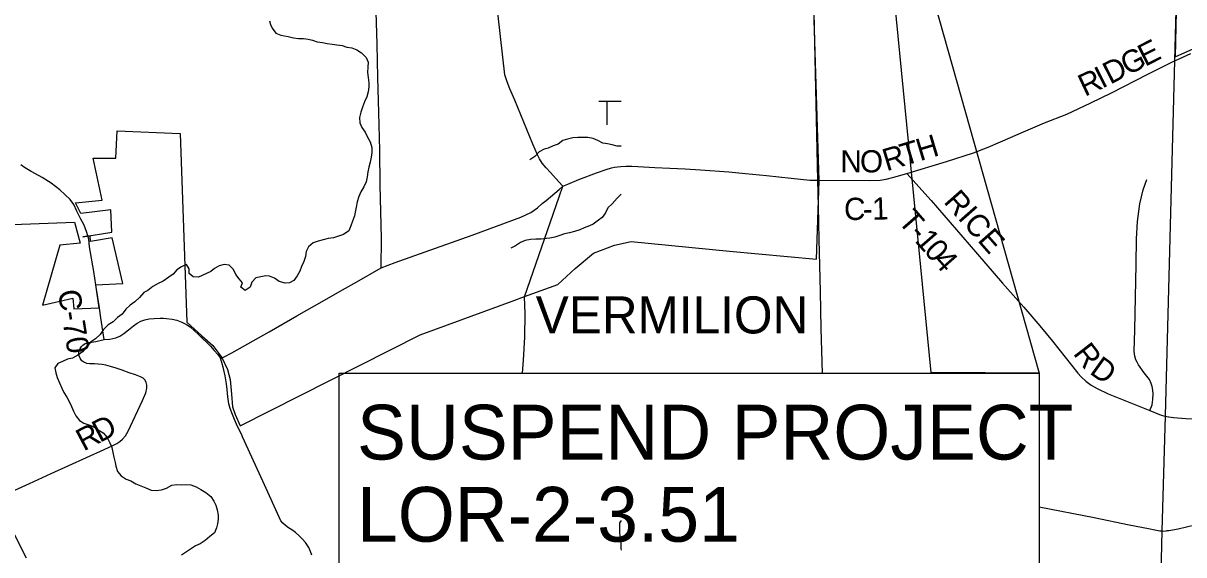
# Model space of a CAD drawing. Extents: x 0 to 34, y 0 to 22.
# Drawn here: x 10.012 to 12.978, y 7.409 to 8.768 of the extents above; entities that cross this region are included whole.
import ezdxf

# ---------------------------------------------------------------- set-up
doc = ezdxf.new("R2010")
doc.units = 0
for name, color, linetype in [('GM_X_City_Street', 7, 'Continuous'), ('GM_X_Corporation', 7, 'Continuous'), ('GM_X_Corporation_Text', 7, 'Continuous'), ('GM_X_County_Road', 7, 'Continuous'), ('GM_X_County_Road_Text', 7, 'Continuous'), ('GM_X_Minor_River', 7, 'Continuous'), ('GM_X_Rail_Line', 7, 'Continuous'), ('GM_X_Township_Road', 7, 'Continuous'), ('GM_X_Township_Road_Text', 7, 'Continuous'), ('SH_Text', 7, 'Continuous')]:
    doc.layers.add(name, color=color, linetype=linetype)

msp = doc.modelspace()

# ---------------------------------------------------------------- linework, layer by layer
at = {"layer": 'GM_X_City_Street'}
msp.add_line((11.5049, 8.5085), (11.5047, 8.5684), dxfattribs=at)
msp.add_lwpolyline([(11.4832, 8.5689), (11.5047, 8.5684), (11.5404, 8.5686)], dxfattribs=at)
at = {"layer": 'GM_X_Corporation'}
for points in [[(12.9927, 10.4066), (12.9728, 9.4593), (12.9564, 8.6818), (13.0041, 8.7033)], [(9.9393, 8.2516), (10.1436, 8.2595), (10.1579, 8.206), (10.1055, 8.2004), (10.0617, 8.0476), (10.1393, 8.0651), (10.1419, 8.0378), (10.2067, 8.041), (10.1977, 8.0993), (10.2671, 8.1024), (10.2396, 8.2192), (10.1846, 8.21), (10.183, 8.225), (10.1645, 8.2225), (10.239, 8.2343), (10.2363, 8.2912), (10.1593, 8.2814), (10.1456, 8.3093), (10.2138, 8.3154), (10.1907, 8.4233), (10.2493, 8.4233), (10.2524, 8.493), (10.4135, 8.4866), (10.4306, 8.0042), (10.4691, 7.9694), (10.497, 7.944), (10.52, 7.9137), (10.534, 7.8827), (10.5411, 7.8576), (10.5446, 7.82), (10.5471, 7.7872), (10.554, 7.7677), (10.5669, 7.7388), (11.0268, 7.9716), (11.2619, 8.0576), (11.2934, 8.0692), (11.3788, 8.1005), (11.4227, 8.1414), (11.47, 8.1805), (11.5231, 8.2005), (11.5663, 8.2099), (11.8168, 8.1857), (12.0394, 8.1648), (12.0462, 8.3651), (12.0135, 9.4352)]]:
    msp.add_lwpolyline(points, dxfattribs=at)
at = {"layer": 'GM_X_County_Road'}
msp.add_line((12.033, 8.3673), (12.0431, 8.3673), dxfattribs=at)
for points in [[(12.0463, 8.2153), (12.0443, 8.3007), (12.0431, 8.3673), (12.0305, 8.953), (12.0238, 9.0638)], [(10.9274, 8.1427), (10.9276, 8.2181), (10.9246, 8.3546), (10.9237, 8.443), (10.9207, 8.5401), (10.9187, 8.6294), (10.9172, 8.7146), (10.9133, 8.8248)], [(12.9572, 8.6731), (12.9961, 8.6909)], [(12.0431, 8.3673), (12.1746, 8.3657), (12.2024, 8.3671), (12.2179, 8.3697), (12.2371, 8.3747), (12.2708, 8.384), (12.372, 8.4143), (12.4412, 8.437), (12.4782, 8.4513), (12.5099, 8.4649), (12.5746, 8.4933), (12.6224, 8.5131), (12.6789, 8.536), (12.7407, 8.5642), (12.7935, 8.5897), (12.8863, 8.6382), (12.9544, 8.6719), (12.9572, 8.6731)], [(10.1978, 8.0997), (10.1928, 8.1335), (10.182, 8.1966), (10.1795, 8.2161), (10.175, 8.2334), (10.1677, 8.2519), (10.1593, 8.2676), (10.1492, 8.2881), (10.1412, 8.3049), (10.1318, 8.3177), (10.1186, 8.3306), (10.1057, 8.342), (10.0838, 8.359), (10.0607, 8.3735), (10.044, 8.3831), (10.0327, 8.3887), (10.0152, 8.3993), (10.0059, 8.4059)], [(11.3909, 8.3514), (11.4039, 8.3568), (11.4325, 8.3686), (11.4772, 8.3853), (11.502, 8.3939), (11.5153, 8.3983), (11.5232, 8.4), (11.531, 8.4013), (11.5394, 8.402), (11.5524, 8.4025), (11.5672, 8.4025), (11.5831, 8.4018), (11.6261, 8.3991), (11.6645, 8.3976), (11.7041, 8.3963), (11.7434, 8.3936), (11.8154, 8.3885), (11.8584, 8.3843), (11.9122, 8.3786), (11.9752, 8.3723), (12.0229, 8.3673), (12.033, 8.3673)], [(11.3711, 8.3338), (11.3823, 8.343), (11.3909, 8.3514)], [(10.5256, 7.9157), (10.5451, 7.9252), (10.6405, 7.9797), (10.7113, 8.02), (10.7821, 8.0603), (10.8279, 8.0863), (10.8647, 8.1072), (10.9274, 8.1427), (10.963, 8.1565), (11.0129, 8.1741), (11.1596, 8.2267), (11.2842, 8.2722), (11.3091, 8.2843), (11.3263, 8.2966), (11.3388, 8.3071), (11.3486, 8.3152), (11.3711, 8.3338)], [(12.0545, 7.8736), (12.0514, 7.9876), (12.0494, 8.0827), (12.0463, 8.2153)], [(10.2071, 8.0394), (10.207, 8.0404), (10.1987, 8.0938), (10.198, 8.0987), (10.1978, 8.0997)], [(10.2192, 7.9594), (10.2109, 8.0151), (10.2071, 8.0394)], [(10.2192, 7.9594), (10.2332, 7.9608), (10.2487, 7.964), (10.2593, 7.9684), (10.2694, 7.9748), (10.2816, 7.9844), (10.2944, 7.995), (10.3033, 8.0014), (10.3129, 8.0063), (10.3229, 8.0097), (10.334, 8.0122), (10.3473, 8.0136), (10.3623, 8.0141), (10.3709, 8.0144), (10.3785, 8.0134), (10.393, 8.0117), (10.405, 8.0087), (10.4176, 8.0043), (10.4291, 7.9982), (10.4385, 7.9918), (10.4498, 7.9822), (10.4591, 7.9733), (10.4712, 7.9618), (10.4798, 7.9534), (10.4906, 7.9426), (10.5004, 7.932), (10.51, 7.9215), (10.5162, 7.9117)], [(10.3034, 7.8675), (10.2989, 7.8691), (10.2834, 7.8745), (10.2654, 7.8809), (10.2497, 7.8866), (10.2354, 7.891), (10.2234, 7.8942), (10.2136, 7.8959), (10.2037, 7.8964), (10.1946, 7.8971), (10.1826, 7.8974), (10.175, 7.8984), (10.1669, 7.9018), (10.1622, 7.9055), (10.1583, 7.9107), (10.1556, 7.918), (10.1546, 7.9247), (10.1556, 7.9318), (10.1575, 7.9365), (10.161, 7.9421), (10.1649, 7.9456), (10.1706, 7.9492), (10.1806, 7.952), (10.1981, 7.9544), (10.2192, 7.9594)], [(10.5162, 7.9117), (10.5202, 7.9132), (10.5256, 7.9157)], [(10.5727, 7.7108), (10.5714, 7.7135), (10.5577, 7.7435), (10.5525, 7.7556), (10.5469, 7.7676), (10.5415, 7.7831), (10.538, 7.7954), (10.5351, 7.8133), (10.5336, 7.8315), (10.5319, 7.8467), (10.5287, 7.8672), (10.5242, 7.8856), (10.5201, 7.9011), (10.5162, 7.9117)], [(9.9533, 7.5576), (10.028, 7.5914), (10.084, 7.6169), (10.1737, 7.6585), (10.2187, 7.6784), (10.2413, 7.6889), (10.2514, 7.6941), (10.2588, 7.699), (10.2662, 7.7052), (10.2733, 7.7133), (10.2807, 7.7256), (10.317, 7.8042), (10.3252, 7.8234), (10.3279, 7.8354), (10.3281, 7.8433), (10.3266, 7.8497), (10.3237, 7.8558), (10.319, 7.8605), (10.3116, 7.8647), (10.3034, 7.8675)], [(10.7496, 7.4085), (10.7467, 7.4181), (10.7418, 7.4282), (10.7334, 7.4409), (10.7251, 7.45), (10.7167, 7.4584), (10.7081, 7.4668), (10.699, 7.4731), (10.6902, 7.4786), (10.6823, 7.4844), (10.6754, 7.4903), (10.6706, 7.4962), (10.6246, 7.5972), (10.5727, 7.7108)]]:
    msp.add_lwpolyline(points, dxfattribs=at)
at = {"layer": 'GM_X_Minor_River'}
for points in [[(10.6414, 8.7743), (10.6445, 8.7648), (10.6484, 8.755), (10.6576, 8.7429), (10.6706, 8.7377), (10.6801, 8.7355), (10.6896, 8.7344), (10.7026, 8.7311), (10.7159, 8.7293), (10.7288, 8.7287), (10.7402, 8.7273), (10.7516, 8.7247), (10.7638, 8.7206), (10.7768, 8.7188), (10.7893, 8.7159), (10.8019, 8.7141), (10.8137, 8.7131), (10.827, 8.7113), (10.8396, 8.7072), (10.8522, 8.7047), (10.8647, 8.7002), (10.8766, 8.6927), (10.8888, 8.6807), (10.8935, 8.6689), (10.8929, 8.656), (10.8922, 8.6423), (10.8938, 8.629), (10.8955, 8.6153), (10.8955, 8.6058), (10.8938, 8.5928), (10.8901, 8.5802), (10.8845, 8.5672), (10.8792, 8.5539), (10.8748, 8.5405), (10.8719, 8.5272), (10.8724, 8.5138), (10.8774, 8.5017), (10.8862, 8.4892), (10.8924, 8.4767), (10.8986, 8.4646), (10.9029, 8.4506), (10.9034, 8.4376), (10.9016, 8.4258), (10.8986, 8.4129), (10.8953, 8.3999), (10.8928, 8.3881), (10.891, 8.3755), (10.8884, 8.3625), (10.8828, 8.3499), (10.8749, 8.3373), (10.8701, 8.3251), (10.866, 8.3114), (10.8627, 8.298), (10.8602, 8.2854), (10.8587, 8.2759), (10.8539, 8.2622), (10.8491, 8.2499), (10.8446, 8.2373), (10.831, 8.2281), (10.8177, 8.2238), (10.8048, 8.2195), (10.7915, 8.2174), (10.7786, 8.2143), (10.7661, 8.2107), (10.7532, 8.2064), (10.7412, 8.1964), (10.7356, 8.1842), (10.7338, 8.1716), (10.7297, 8.159), (10.7237, 8.1464), (10.7192, 8.1342), (10.7121, 8.122), (10.7035, 8.1105), (10.6929, 8.1047), (10.6815, 8.1034), (10.6666, 8.1082), (10.6544, 8.1161), (10.6418, 8.1213), (10.6319, 8.1224), (10.6198, 8.1196), (10.6065, 8.1172), (10.5963, 8.1065), (10.5922, 8.0931), (10.5794, 8.0846), (10.5683, 8.0936), (10.5724, 8.1043), (10.5643, 8.1149), (10.5559, 8.1259), (10.55, 8.1388), (10.5389, 8.1497), (10.526, 8.1511)], [(11.5404, 8.4538), (11.5303, 8.4537), (11.5173, 8.457), (11.5051, 8.4596), (11.4937, 8.4618), (11.4811, 8.4682), (11.4689, 8.4738), (11.4552, 8.4756), (11.4415, 8.4759), (11.4293, 8.4762), (11.4168, 8.475), (11.4031, 8.4719), (11.3917, 8.468), (11.3796, 8.4591), (11.3668, 8.4549), (11.3539, 8.4487), (11.344, 8.4463), (11.3308, 8.439), (11.3195, 8.4275), (11.307, 8.4191)], [(11.5404, 8.331), (11.5401, 8.3309), (11.5299, 8.3205), (11.5171, 8.3067), (11.5061, 8.296), (11.5002, 8.2834), (11.4919, 8.2719), (11.4821, 8.2646), (11.4692, 8.2543), (11.4594, 8.2504), (11.4461, 8.245), (11.4344, 8.2403), (11.4207, 8.2357), (11.4082, 8.2322), (11.3957, 8.2294), (11.3835, 8.2255), (11.371, 8.2216), (11.3581, 8.2185), (11.3483, 8.2177), (11.3361, 8.2161), (11.3224, 8.216), (11.3083, 8.2151), (11.2954, 8.2128), (11.2829, 8.2073), (11.2705, 8.1993), (11.2583, 8.1931)], [(10.4915, 8.1338), (10.4601, 8.1193), (10.4464, 8.1196), (10.4361, 8.1282), (10.4364, 8.14), (10.4295, 8.151), (10.417, 8.1455), (10.4049, 8.1378), (10.3958, 8.1263), (10.3841, 8.119), (10.3697, 8.109), (10.3569, 8.1024), (10.3436, 8.095), (10.3304, 8.085), (10.3206, 8.08), (10.3096, 8.0673), (10.2979, 8.0562), (10.2855, 8.0477), (10.2742, 8.0369), (10.2651, 8.0247), (10.2534, 8.0162), (10.2417, 8.0051), (10.2289, 7.9969), (10.2176, 7.985), (10.2085, 7.9728), (10.1969, 7.9616), (10.1844, 7.9528), (10.1738, 7.9405), (10.1641, 7.9279), (10.1516, 7.9194), (10.1383, 7.9124), (10.1254, 7.9096), (10.1126, 7.9038), (10.1004, 7.8984), (10.0929, 7.8876), (10.0957, 7.8747), (10.0988, 7.8622), (10.105, 7.8489), (10.1108, 7.8357), (10.1159, 7.8243), (10.1236, 7.8122), (10.1305, 7.7997), (10.1359, 7.7883), (10.141, 7.7762), (10.1468, 7.7648), (10.156, 7.7531), (10.1675, 7.746), (10.18, 7.7416), (10.1915, 7.7375), (10.2037, 7.7288), (10.2163, 7.7213), (10.2267, 7.7089), (10.234, 7.6952), (10.2387, 7.6835), (10.2411, 7.6709), (10.2434, 7.6592), (10.2473, 7.6455), (10.2493, 7.6356), (10.2536, 7.622), (10.2624, 7.611), (10.2751, 7.6031), (10.2873, 7.5983), (10.3002, 7.5912), (10.3125, 7.586), (10.3254, 7.5804), (10.3388, 7.5748), (10.3517, 7.5734), (10.3654, 7.5758), (10.3783, 7.5797), (10.3919, 7.5875), (10.4048, 7.5895), (10.4177, 7.5885), (10.4272, 7.5889), (10.4405, 7.5879), (10.4539, 7.5831), (10.4665, 7.576), (10.4787, 7.5685), (10.4917, 7.5587), (10.499, 7.5466), (10.5044, 7.5367), (10.508, 7.5242), (10.5103, 7.5105), (10.5104, 7.5006), (10.509, 7.4885), (10.5064, 7.4782), (10.5012, 7.4656), (10.4891, 7.4559), (10.4774, 7.4463), (10.4642, 7.4378), (10.4525, 7.432), (10.4426, 7.4254), (10.4298, 7.417), (10.4169, 7.4088)], [(10.526, 8.1511), (10.5131, 8.1479), (10.5014, 8.1414), (10.4915, 8.1338)], [(11.5404, 7.497), (11.5362, 7.4914), (11.5359, 7.4789), (11.536, 7.4656), (11.5381, 7.4522), (11.5393, 7.4393), (11.5398, 7.426), (11.5404, 7.4216)]]:
    msp.add_lwpolyline(points, dxfattribs=at)
at = {"layer": 'GM_X_Rail_Line'}
msp.add_lwpolyline([(14.1135, 5.8645), (14.1135, 10.4074), (12.9952, 10.4123), (12.9843, 9.8218), (12.975, 9.4666), (12.9697, 9.2637), (12.9695, 9.2552), (12.9694, 9.2509), (12.9542, 8.6724), (12.9304, 7.7644), (12.9222, 7.4711), (12.9186, 7.3231), (12.9183, 7.3117), (12.9181, 7.3048), (12.8807, 5.8723), (13.2678, 5.8695), (13.384, 5.8688), (13.5036, 5.8681)], close=True, dxfattribs=at)
at = {"layer": 'GM_X_Township_Road'}
for p, q in [((11.3815, 8.324), (11.3909, 8.3514)), ((11.2936, 8.0686), (11.3815, 8.324)), ((12.9333, 7.471), (12.9361, 7.4714))]:
    msp.add_line(p, q, dxfattribs=at)
for points in [[(11.3909, 8.3514), (11.3808, 8.363), (11.3598, 8.3866), (11.3484, 8.3988), (11.3388, 8.4107), (11.3319, 8.4212), (11.3267, 8.432), (11.315, 8.4585), (11.2682, 8.5711), (11.2555, 8.6007), (11.2486, 8.6184), (11.2455, 8.6282), (11.243, 8.6358), (11.22, 8.8408)], [(12.2708, 8.384), (12.3327, 8.3147), (12.43, 8.2025), (12.5145, 8.104), (12.569, 8.0426), (12.6099, 7.9949), (12.6429, 7.9552), (12.7078, 7.8734), (12.7158, 7.8647), (12.7277, 7.8533), (12.7416, 7.8428), (12.7571, 7.8341), (12.7851, 7.8212), (12.8918, 7.778), (12.9163, 7.7679), (12.9237, 7.7657), (12.9306, 7.7639), (12.9391, 7.762)], [(12.8918, 7.778), (12.8973, 7.793), (12.8995, 7.8062), (12.8997, 7.8209), (12.899, 7.8305), (12.8973, 7.8393), (12.8952, 7.8472), (12.8902, 7.8577), (12.8773, 7.8749), (12.8625, 7.8949), (12.8589, 7.9014), (12.8558, 7.9076), (12.8529, 7.9169), (12.8517, 7.9286), (12.8527, 7.9844), (12.8567, 8.151), (12.8577, 8.2172), (12.8598, 8.2613), (12.866, 8.3064), (12.8746, 8.3418), (12.8794, 8.3563), (12.884, 8.369)], [(11.2882, 7.8736), (11.2908, 7.9071), (11.2942, 7.9653), (11.2946, 8.0265), (11.2936, 8.0686)], [(12.9391, 7.762), (12.94, 7.7618), (12.9522, 7.7601), (12.9831, 7.758), (13.0217, 7.7565), (13.0775, 7.7544), (13.1322, 7.7524), (13.1623, 7.7508), (13.1899, 7.7486), (13.216, 7.7458), (13.2429, 7.7415), (13.2649, 7.7372), (13.2797, 7.7331), (13.3074, 7.7252), (13.3477, 7.7138), (13.4179, 7.6933), (13.4632, 7.6796), (13.5062, 7.672), (13.551, 7.6644), (13.6011, 7.658)], [(12.9361, 7.4714), (12.9399, 7.4719), (12.9638, 7.4761), (13.0493, 7.496), (13.1117, 7.5095), (13.185, 7.5265), (13.2292, 7.5378), (13.2629, 7.5481), (13.2916, 7.5577), (13.3128, 7.5643), (13.3359, 7.5729), (13.3681, 7.5842), (13.403, 7.597), (13.4504, 7.613), (13.4605, 7.6167), (13.4684, 7.6189), (13.4755, 7.6201), (13.4829, 7.6201), (13.4981, 7.6196), (13.5524, 7.6177), (13.5982, 7.6167)], [(12.6083, 7.5324), (12.7494, 7.5051), (12.8386, 7.4864), (12.8878, 7.4763), (12.9038, 7.4729), (12.9173, 7.4709), (12.9225, 7.4706), (12.9276, 7.4702), (12.9333, 7.471)], [(10.0206, 7.4011), (9.9911, 7.4594)]]:
    msp.add_lwpolyline(points, dxfattribs=at)
at = {"layer": 'SH_Text'}
for points in [[(12.3328, 7.875), (12.186, 9.3696), (12.6083, 7.8736)], [(10.8199, 7.8736), (12.6083, 7.8736), (12.6083, 7.1619), (10.8199, 7.1619)]]:
    msp.add_lwpolyline(points, close=True, dxfattribs=at)

# ---------------------------------------------------------------- texts
at = {"layer": 'GM_X_Corporation_Text'}
msp.add_text('VERMILION', height=0.0947, rotation=0, dxfattribs=at).set_placement((11.322, 7.9752))
at = {"layer": 'GM_X_County_Road_Text'}
for s, height, rotation, p in [('E', 0.0568, 26.9829, (12.8793, 8.6562)), ('G', 0.0568, 26.9928, (12.8347, 8.6335)), ('D', 0.0568, 26.9768, (12.7901, 8.6108)), ('R', 0.0568, 25.1895, (12.7254, 8.5795)), ('I', 0.0568, 26.9134, (12.7693, 8.6002)), ('H', 0.0568, 16.6469, (12.304, 8.4152)), ('R', 0.0568, 16.8759, (12.2186, 8.3894)), ('T', 0.0568, 16.6471, (12.2632, 8.403)), ('N', 0.0568, 0, (12.1006, 8.3867)), ('O', 0.0568, 0.0957, (12.1507, 8.3867)), ('C', 0.0568, 359.1726, (12.1094, 8.2656)), ('1', 0.0568, 2.0083, (12.1825, 8.2653)), ('-', 0.0568, 0.699, (12.1577, 8.265)), ('C-70', 0.05682, 278.9553, (10.1006, 8.0832)), ('R', 0.0568, 27.904, (10.1667, 7.6732)), ('D', 0.0568, 27.6941, (10.2079, 7.695))]:
    msp.add_text(s, height=height, rotation=rotation, dxfattribs=at).set_placement(p)
at = {"layer": 'GM_X_Township_Road_Text'}
for s, height, rotation, p in [('RICE', 0.05682, 311.3832, (12.3625, 8.3107)), ('T', 0.0568, 311.1303, (12.2455, 8.2611)), ('-', 0.0568, 311.1455, (12.2735, 8.2291)), ('1', 0.0568, 311.1438, (12.2888, 8.2115)), ('0', 0.0568, 311.2299, (12.3119, 8.1851)), ('4', 0.0568, 311.5123, (12.3352, 8.1586)), ('R', 0.0568, 307.6022, (12.6936, 7.9234)), ('D', 0.0568, 324.5535, (12.735, 7.874))]:
    msp.add_text(s, height=height, rotation=rotation, dxfattribs=at).set_placement(p)
at = {"layer": 'SH_Text'}
for s, p in [('SUSPEND PROJECT', (10.8654, 7.6529)), ('LOR-2-3.51', (10.8654, 7.4429))]:
    msp.add_text(s, height=0.14, dxfattribs=at).set_placement(p)

doc.saveas('drawing.dxf')
